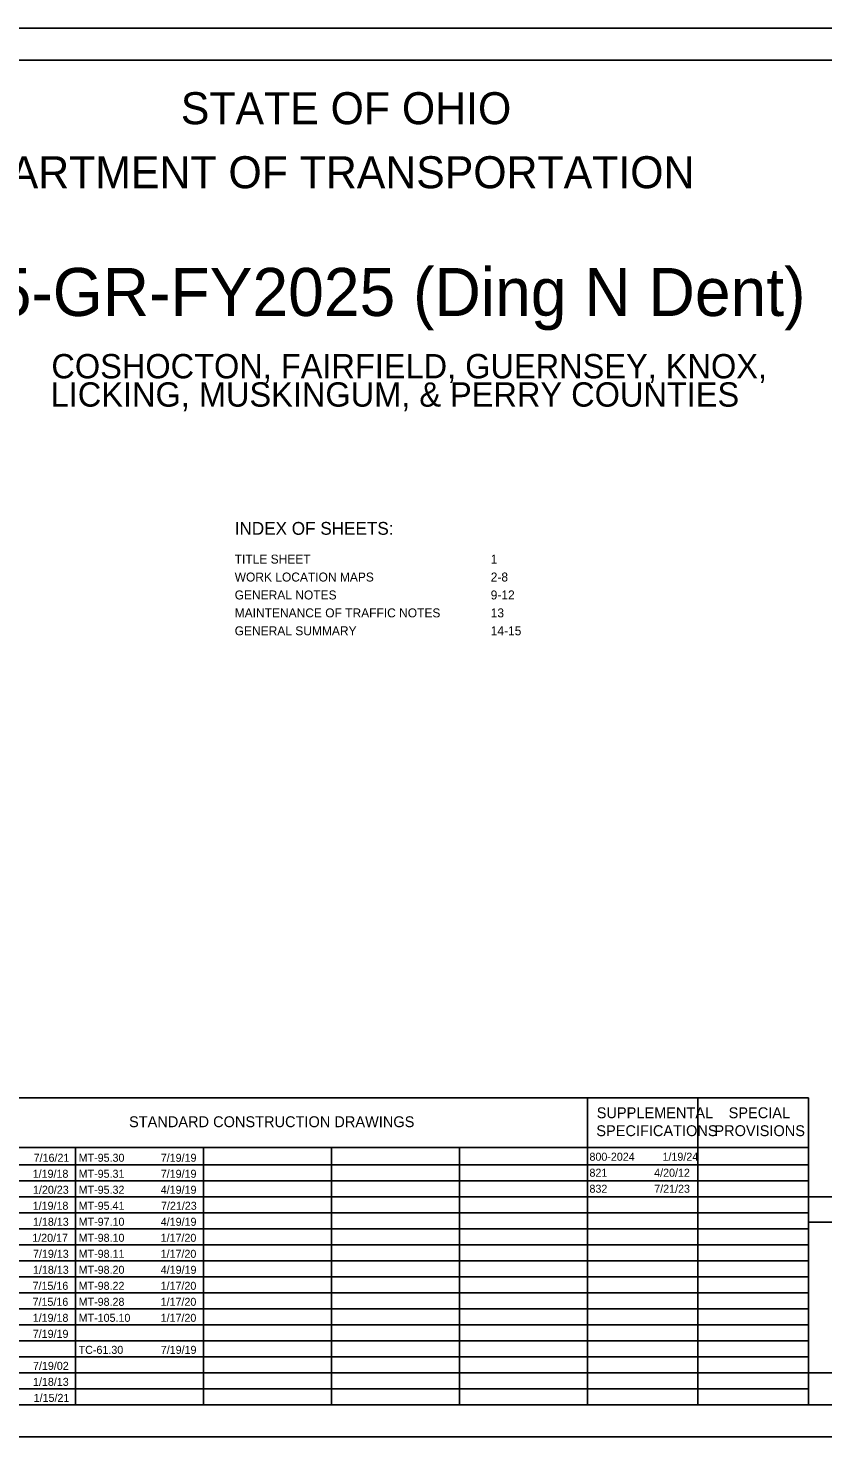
# Model space of a CAD drawing. Extents: x 0 to 34, y 0 to 22.
# Drawn here: x 11.41 to 23.83, y 0 to 22 of the extents above; entities that cross this region are included whole.
import ezdxf

# ---------------------------------------------------------------- set-up
doc = ezdxf.new("R2010")
doc.units = 0
for name, color, linetype in [('Default', 7, 'Continuous'), ('SH_Border', 7, 'Continuous'), ('SH_Cut_Line', 7, 'Continuous'), ('SH_Data', 7, 'Continuous'), ('SH_Text', 7, 'Continuous')]:
    doc.layers.add(name, color=color, linetype=linetype)

msp = doc.modelspace()

# ---------------------------------------------------------------- linework, layer by layer
at = {"layer": 'SH_Border'}
msp.add_lwpolyline([(1.5, 21.5), (33.5, 21.5), (33.5, 0.5), (1.5, 0.5)], close=True, dxfattribs=at)
at = {"layer": 'SH_Cut_Line'}
msp.add_lwpolyline([(0, 0), (34, 0), (34, 22), (0, 22)], close=True, dxfattribs=at)
at = {"layer": 'SH_Data'}
for p, q in [((10.15, 5.292), (23.6, 5.292)), ((20.15, 0.5), (20.15, 5.292)), ((21.875, 0.5), (21.875, 5.292)), ((23.6, 0.5), (23.6, 5.292)), ((10.15, 4.521), (23.6, 4.521)), ((12.15, 0.5), (12.15, 4.521)), ((14.15, 0.5), (14.15, 4.521)), ((16.15, 0.5), (16.15, 4.521)), ((18.15, 0.5), (18.15, 4.521)), ((10.15, 4.25), (23.6, 4.25)), ((10.15, 4), (23.6, 4)), ((10.15, 3.75), (23.6, 3.75)), ((23.6, 0.5), (23.6, 3.75)), ((23.6, 3.75), (26.4, 3.75)), ((10.15, 3.5), (23.6, 3.5)), ((23.6, 3.35), (26.4, 3.35)), ((10.15, 3.25), (23.6, 3.25)), ((10.15, 3), (23.6, 3)), ((10.15, 2.75), (23.6, 2.75)), ((10.15, 2.5), (23.6, 2.5)), ((10.15, 2.25), (23.6, 2.25)), ((10.15, 2), (23.6, 2)), ((10.15, 1.75), (23.6, 1.75)), ((10.15, 1.5), (23.6, 1.5)), ((10.15, 1.25), (23.6, 1.25)), ((10.15, 1), (23.6, 1)), ((10.15, 0.75), (23.6, 0.75)), ((23.6, 0.5), (26.4, 0.5))]:
    msp.add_line(p, q, dxfattribs=at)
msp.add_lwpolyline([(23.6, 0.5), (23.6, 1), (26.4, 1), (26.4, 0.5)], close=True, dxfattribs=at)

# ---------------------------------------------------------------- texts
at = {"layer": 'Default'}
for s, p in [('7/16/21', (11.496, 4.296)), ('MT-95.30', (12.199, 4.296)), ('7/19/19', (13.482, 4.296)), ('800-2024', (20.18, 4.312)), ('1/19/24', (21.321, 4.312)), ('821', (20.18, 4.062)), ('4/20/12', (21.191, 4.062)), ('1/19/18', (11.481, 4.046)), ('MT-95.31', (12.199, 4.046)), ('7/19/19', (13.482, 4.046)), ('1/20/23', (11.486, 3.796)), ('MT-95.32', (12.199, 3.796)), ('4/19/19', (13.482, 3.796)), ('832', (20.18, 3.812)), ('7/21/23', (21.192, 3.812)), ('1/19/18', (11.481, 3.546)), ('MT-95.41', (12.199, 3.546)), ('7/21/23', (13.486, 3.546)), ('1/18/13', (11.486, 3.296)), ('MT-97.10', (12.199, 3.296)), ('4/19/19', (13.482, 3.296)), ('1/20/17', (11.474, 3.046)), ('MT-98.10', (12.199, 3.046)), ('1/17/20', (13.48, 3.046)), ('7/19/13', (11.486, 2.796)), ('MT-98.11', (12.199, 2.796)), ('1/17/20', (13.48, 2.796)), ('1/18/13', (11.486, 2.546)), ('MT-98.20', (12.199, 2.546)), ('4/19/19', (13.482, 2.546)), ('7/15/16', (11.479, 2.296)), ('MT-98.22', (12.199, 2.296)), ('1/17/20', (13.48, 2.296)), ('7/15/16', (11.479, 2.046)), ('MT-98.28', (12.199, 2.046)), ('1/17/20', (13.48, 2.046)), ('1/19/18', (11.481, 1.796)), ('MT-105.10', (12.199, 1.796)), ('1/17/20', (13.48, 1.796)), ('7/19/19', (11.482, 1.546)), ('TC-61.30', (12.199, 1.296)), ('7/19/19', (13.482, 1.296)), ('7/19/02', (11.486, 1.046)), ('1/18/13', (11.486, 0.796)), ('1/15/21', (11.496, 0.546))]:
    msp.add_text(s, height=0.125, dxfattribs=at).set_placement(p)
at = {"layer": 'SH_Text'}
for s, height, p in [('STATE OF OHIO', 0.5, (13.795, 20.5)), ('DEPARTMENT OF TRANSPORTATION', 0.5, (9.747, 19.5)), ('D05-GR-FY2025 (Ding N Dent)', 0.75, (9.621, 17.505)), ('COSHOCTON, FAIRFIELD, GUERNSEY, KNOX,', 0.38, (11.773, 16.531)), ('LICKING, MUSKINGUM, & PERRY COUNTIES', 0.38, (11.762, 16.089)), ('INDEX OF SHEETS:', 0.2, (14.637, 14.088)), ('TITLE SHEET', 0.14, (14.637, 13.638)), ('1', 0.14, (18.637, 13.638)), ('WORK LOCATION MAPS', 0.14, (14.637, 13.358)), ('2-8', 0.14, (18.637, 13.358)), ('GENERAL NOTES', 0.14, (14.637, 13.078)), ('9-12', 0.14, (18.637, 13.078)), ('MAINTENANCE OF TRAFFIC NOTES', 0.14, (14.637, 12.798)), ('13', 0.14, (18.637, 12.798)), ('GENERAL SUMMARY', 0.14, (14.637, 12.518)), ('14-15', 0.14, (18.637, 12.518)), ('SUPPLEMENTAL', 0.17, (20.293, 4.976)), ('SPECIAL', 0.17, (22.354, 4.976)), ('STANDARD CONSTRUCTION DRAWINGS', 0.17, (12.986, 4.836)), ('SPECIFICATIONS', 0.17, (20.287, 4.696)), ('PROVISIONS', 0.17, (22.132, 4.696))]:
    msp.add_text(s, height=height, dxfattribs=at).set_placement(p)

doc.saveas('drawing.dxf')
